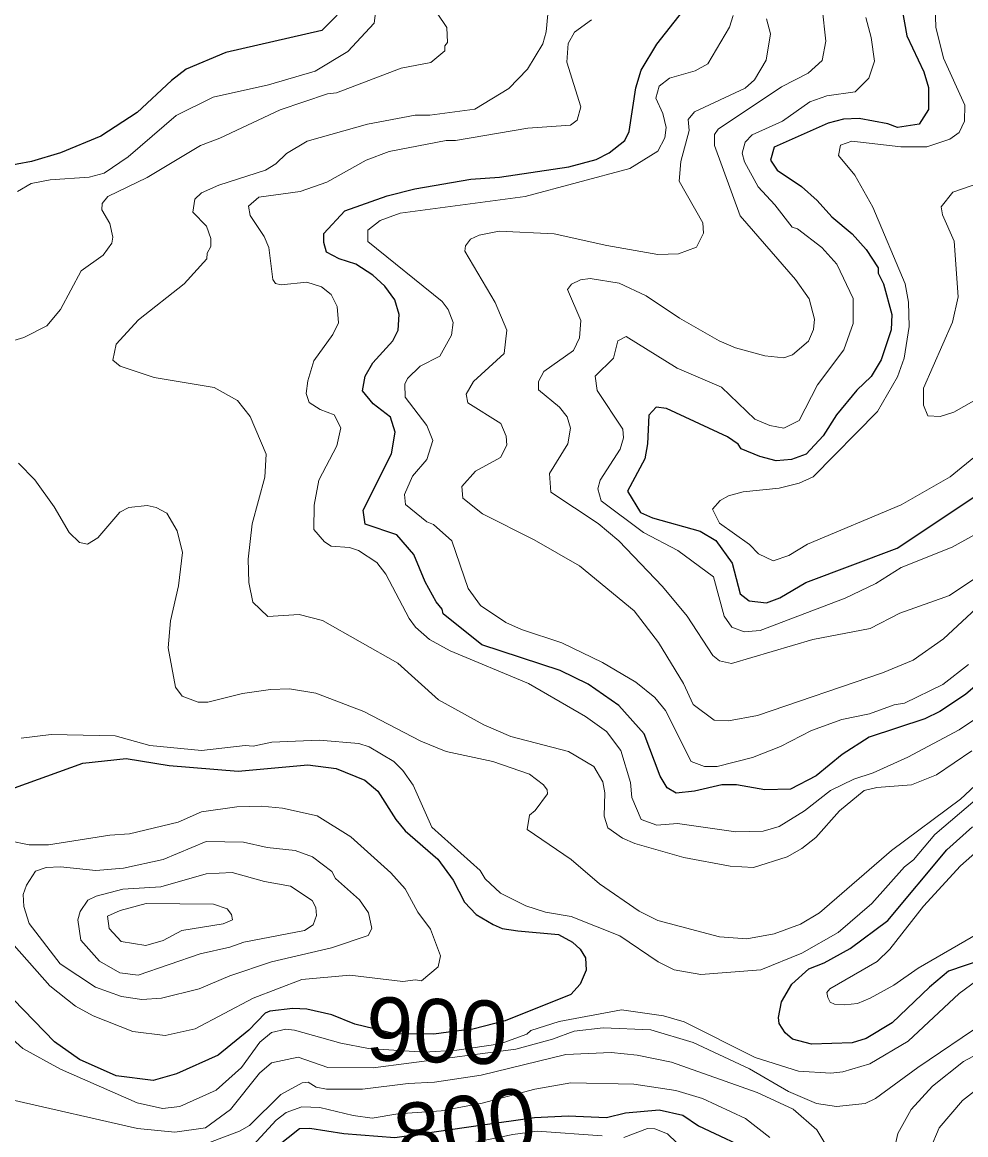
# Model space of a CAD drawing. Extents: x 673.3 to 698.5, y 6984.3 to 7012.3.
# Drawn here: x 685.086 to 686.277, y 6996.366 to 6997.77 of the extents above; entities that cross this region are included whole.
import ezdxf
from ezdxf.enums import TextEntityAlignment as Align

# ---------------------------------------------------------------- set-up
doc = ezdxf.new("R2010")
doc.units = 0
doc.header["$LTSCALE"] = 0.032
doc.layers.add('1', color=7, linetype='Continuous', lineweight=25)
doc.layers.add('2', color=7, linetype='Continuous', lineweight=13)
doc.layers.add('61', color=7, linetype='Continuous')

msp = doc.modelspace()

# ---------------------------------------------------------------- linework, layer by layer
at = {"layer": '1'}
for points in [[(686.3361, 6996.9726), (686.2772, 6996.9217), (686.2448, 6996.9002), (686.2259, 6996.8908), (686.1553, 6996.8677), (686.1213, 6996.8458), (686.0884, 6996.819), (686.0559, 6996.8018), (686.0239, 6996.801), (685.9881, 6996.8075), (685.9695, 6996.8075), (685.9349, 6996.7993), (685.9116, 6996.7969), (685.9005, 6996.8037), (685.8915, 6996.8185), (685.8713, 6996.8719), (685.8395, 6996.9077), (685.8004, 6996.9345), (685.7654, 6996.9517), (685.6662, 6996.9843), (685.6175, 6997.0232), (685.6162, 6997.0292), (685.6084, 6997.0386), (685.5946, 6997.0637), (685.5806, 6997.0983), (685.559, 6997.123), (685.519, 6997.1365), (685.5163, 6997.1544), (685.5521, 6997.2253), (685.5569, 6997.2529), (685.5511, 6997.2717), (685.529, 6997.2883), (685.5157, 6997.3049), (685.5189, 6997.3233), (685.5288, 6997.3403), (685.5537, 6997.3678), (685.5608, 6997.3813), (685.5618, 6997.4012), (685.5566, 6997.4198), (685.5439, 6997.437), (685.5287, 6997.4507), (685.5073, 6997.4647), (685.4861, 6997.4716), (685.4701, 6997.4801), (685.4666, 6997.4922), (685.4669, 6997.5035), (685.4933, 6997.5322), (685.5467, 6997.5511), (685.5815, 6997.5599), (685.6525, 6997.5723), (685.6884, 6997.5748), (685.776, 6997.5877), (685.8105, 6997.5968), (685.8271, 6997.6053), (685.8468, 6997.6211), (685.8525, 6997.6323), (685.8608, 6997.6874), (685.8676, 6997.7097), (685.8872, 6997.7426), (685.9311, 6997.7987)], [(686.1972, 6997.7859), (686.2029, 6997.753), (686.2247, 6997.7074), (686.2304, 6997.6879), (686.2305, 6997.6599), (686.2187, 6997.6414), (686.1914, 6997.6375), (686.1792, 6997.642), (686.1428, 6997.6488), (686.1229, 6997.648), (686.1035, 6997.643), (686.0356, 6997.6123), (686.031, 6997.5961), (686.0394, 6997.5834), (686.0699, 6997.5627), (686.0898, 6997.5451), (686.1082, 6997.5244), (686.1341, 6997.5032), (686.1518, 6997.4833), (686.1667, 6997.4601), (686.167, 6997.4533), (686.1735, 6997.44), (686.184, 6997.4012), (686.1832, 6997.3817), (686.1708, 6997.344), (686.1578, 6997.3228), (686.1398, 6997.3057), (686.1141, 6997.2747), (686.0975, 6997.2479), (686.0759, 6997.2248), (686.0575, 6997.218), (686.038, 6997.2164), (686.0174, 6997.2218), (685.9937, 6997.2318), (685.9899, 6997.2377), (685.9764, 6997.2469), (685.8994, 6997.2826), (685.8865, 6997.2844)], [(685.4837, 6997.7792), (685.4641, 6997.7596), (685.3431, 6997.7319), (685.293, 6997.711), (685.2743, 6997.6968), (685.2312, 6997.6562), (685.1851, 6997.6262), (685.134, 6997.6052), (685.0976, 6997.5944), (685.0613, 6997.5878)], [(685.8865, 6997.2844), (685.877, 6997.2742), (685.8754, 6997.238), (685.8721, 6997.2189), (685.8501, 6997.1784), (685.8665, 6997.1513), (685.8819, 6997.1447), (685.9422, 6997.1276), (685.9617, 6997.1161), (685.9826, 6997.0874), (685.9927, 6997.0487), (686.0041, 6997.0397), (686.026, 6997.0372), (686.0428, 6997.0436), (686.0755, 6997.0631), (686.1909, 6997.1063), (686.3064, 6997.1831)], [(685.0608, 6996.7981), (685.1623, 6996.8349), (685.2171, 6996.8409), (685.2714, 6996.8319), (685.3584, 6996.8247), (685.4467, 6996.8327), (685.4825, 6996.828), (685.5187, 6996.8132), (685.5349, 6996.7993), (685.5575, 6996.7638), (685.5695, 6996.7494), (685.6109, 6996.7136), (685.6301, 6996.6873), (685.6445, 6996.6592), (685.659, 6996.6437), (685.6805, 6996.6312), (685.692, 6996.6262), (685.7116, 6996.6232), (685.763, 6996.6186), (685.7809, 6996.6088), (685.7903, 6996.6001), (685.7972, 6996.5889), (685.7979, 6996.5736), (685.7905, 6996.5557), (685.7787, 6996.5426), (685.6956, 6996.5096), (685.6548, 6996.4991), (685.6334, 6996.4964), (685.6056, 6996.4928), (685.5565, 6996.4933), (685.506, 6996.5053), (685.4767, 6996.517), (685.4454, 6996.5241), (685.4278, 6996.5249), (685.3985, 6996.5218), (685.3925, 6996.5192), (685.3719, 6996.4978), (685.3334, 6996.4663), (685.2806, 6996.4426), (685.2512, 6996.434), (685.2046, 6996.4402), (685.1583, 6996.4606), (685.1267, 6996.4828), (685.0746, 6996.5366)], [(686.2992, 6996.587), (686.2558, 6996.5721), (686.2315, 6996.5522), (686.1846, 6996.5069), (686.1516, 6996.4873), (686.134, 6996.4817), (686.0825, 6996.4801), (686.0587, 6996.4864), (686.0495, 6996.4943), (686.0416, 6996.5063), (686.0408, 6996.5139), (686.0449, 6996.5333), (686.0577, 6996.5557), (686.0794, 6996.5751), (686.0985, 6996.5827), (686.1314, 6996.6008), (686.1789, 6996.6363), (686.2535, 6996.7256), (686.2858, 6996.7545)], [(685.3951, 6996.3411), (685.436, 6996.3734), (685.4489, 6996.3742), (685.4922, 6996.3671), (685.5564, 6996.3621), (685.6647, 6996.3776), (685.7329, 6996.3874), (685.7753, 6996.3895), (685.8236, 6996.3874), (685.8477, 6996.3933), (685.8902, 6996.3971), (685.9202, 6996.3905), (685.9398, 6996.377), (686.0151, 6996.3416)]]:
    msp.add_lwpolyline(points, dxfattribs=at)
at = {"layer": '2'}
for points in [[(685.0798, 6997.5567), (685.0971, 6997.5666), (685.1211, 6997.5714), (685.1704, 6997.5747), (685.1894, 6997.5795), (685.2197, 6997.6001), (685.2801, 6997.6525), (685.3271, 6997.6757), (685.3968, 6997.6912), (685.4558, 6997.7085), (685.4972, 6997.7334), (685.5301, 6997.7689), (685.5349, 6997.8062)], [(686.1912, 6997.3227), (686.1996, 6997.3462), (686.206, 6997.3862), (686.2053, 6997.4168), (686.2011, 6997.44), (686.1603, 6997.5367), (686.1374, 6997.5773), (686.1167, 6997.6018), (686.1191, 6997.6152), (686.1337, 6997.6202), (686.1956, 6997.613), (686.2285, 6997.613), (686.2575, 6997.6225), (686.2693, 6997.6309), (686.2758, 6997.6452), (686.2761, 6997.6656), (686.2494, 6997.7247), (686.2395, 6997.7641), (686.2385, 6997.8042)], [(685.0567, 6997.363), (685.0877, 6997.3721), (685.1169, 6997.3871), (685.1342, 6997.4077), (685.1603, 6997.4564), (685.188, 6997.4762), (685.1991, 6997.4912), (685.2002, 6997.4989), (685.1964, 6997.5163), (685.1865, 6997.5334), (685.1866, 6997.5412), (685.1938, 6997.5501), (685.2437, 6997.574), (685.3108, 6997.6148), (685.3352, 6997.6238), (685.4117, 6997.6597), (685.4714, 6997.6797), (685.4826, 6997.6813), (685.5643, 6997.7123), (685.602, 6997.7195), (685.6194, 6997.7343), (685.6197, 6997.7405), (685.6229, 6997.7448), (685.622, 6997.7636), (685.6097, 6997.7817)], [(685.8398, 6997.441), (685.8737, 6997.4248), (685.9158, 6997.3967), (685.9662, 6997.3679), (685.9868, 6997.3592), (686.0236, 6997.349), (686.0475, 6997.3465), (686.0587, 6997.3505), (686.0789, 6997.3676), (686.0852, 6997.3825), (686.0864, 6997.3952), (686.0795, 6997.421), (686.0624, 6997.4455), (685.9924, 6997.5256), (685.9601, 6997.6147), (685.9601, 6997.6284), (685.9646, 6997.6352), (686.0447, 6997.6885), (686.0784, 6997.706), (686.0962, 6997.7219), (686.1009, 6997.7462), (686.096, 6997.7885)], [(685.7498, 6997.7802), (685.7476, 6997.7582), (685.7433, 6997.7429), (685.7241, 6997.711), (685.7004, 6997.6864), (685.6574, 6997.6603), (685.6005, 6997.653), (685.5819, 6997.6528), (685.5219, 6997.6414), (685.4456, 6997.6199), (685.4196, 6997.6044), (685.4061, 6997.5916), (685.393, 6997.5835), (685.3343, 6997.5647), (685.3121, 6997.5547), (685.3037, 6997.5468), (685.3013, 6997.5306), (685.3185, 6997.5128), (685.324, 6997.497), (685.324, 6997.487), (685.3192, 6997.4786), (685.3188, 6997.4716), (685.2905, 6997.44), (685.2326, 6997.3945), (685.2044, 6997.3637), (685.2003, 6997.3437), (685.2095, 6997.3359), (685.2526, 6997.3219), (685.3284, 6997.309), (685.3576, 6997.2927), (685.3737, 6997.2725), (685.394, 6997.225), (685.3924, 6997.196), (685.3764, 6997.137), (685.3713, 6997.0924), (685.3721, 6997.0627), (685.3769, 6997.0379), (685.396, 6997.0201), (685.4356, 6997.0225), (685.4649, 6997.0151), (685.5604, 6996.961), (685.6117, 6996.9147)], [(685.9836, 6997.7789), (685.9791, 6997.7642), (685.9515, 6997.7179), (685.9359, 6997.7088), (685.9033, 6997.6994), (685.8902, 6997.6897), (685.886, 6997.6743), (685.895, 6997.655), (685.8989, 6997.6372), (685.8975, 6997.6242), (685.8886, 6997.6074), (685.8532, 6997.5855), (685.7209, 6997.5503), (685.563, 6997.5291), (685.538, 6997.52), (685.5221, 6997.5079), (685.5222, 6997.4932), (685.6162, 6997.4177), (685.6238, 6997.4075), (685.6302, 6997.3911), (685.6278, 6997.3751), (685.6132, 6997.3487), (685.5886, 6997.3359), (685.5725, 6997.3205), (685.569, 6997.3132), (685.5695, 6997.297), (685.5968, 6997.2611), (685.6042, 6997.2423), (685.5968, 6997.2182), (685.5787, 6997.1971), (685.5687, 6997.1741), (685.57, 6997.1612), (685.5968, 6997.1395), (685.6051, 6997.1363), (685.6284, 6997.1154), (685.6492, 6997.0554), (685.6644, 6997.034), (685.6967, 6997.0124), (685.7164, 6997.0035), (685.7674, 6996.9869), (685.8187, 6996.9621), (685.8607, 6996.937), (685.8849, 6996.9176), (685.8981, 6996.9012), (685.9306, 6996.8371), (685.9475, 6996.8308)], [(686.3491, 6997.0842), (686.2495, 6996.9919), (686.2112, 6996.9649), (686.1725, 6996.9487), (686.0143, 6996.8951), (685.9776, 6996.8883), (685.9595, 6996.889), (685.9332, 6996.9088), (685.9209, 6996.9354), (685.8894, 6996.9873), (685.8586, 6997.0271), (685.7896, 6997.0838), (685.7323, 6997.1168), (685.6672, 6997.1494), (685.6422, 6997.1695), (685.6409, 6997.1843), (685.6582, 6997.2034), (685.6899, 6997.2209), (685.6978, 6997.2362), (685.697, 6997.2478), (685.6904, 6997.2636), (685.6488, 6997.2898), (685.6467, 6997.3007), (685.6557, 6997.3167), (685.6946, 6997.3519), (685.6979, 6997.3816), (685.683, 6997.4162), (685.645, 6997.481), (685.6457, 6997.4878), (685.6521, 6997.4962), (685.6631, 6997.5013), (685.6882, 6997.5063), (685.7578, 6997.5031), (685.824, 6997.4882), (685.8887, 6997.4769), (685.9148, 6997.4778), (685.9373, 6997.4862), (685.9462, 6997.5041), (685.9454, 6997.5168), (685.9153, 6997.5694), (685.9176, 6997.5944), (685.9282, 6997.6334), (685.9269, 6997.6474), (685.9347, 6997.6572), (685.9989, 6997.6869), (686.0106, 6997.6977), (686.0253, 6997.7224), (686.0308, 6997.7556), (686.026, 6997.7745)], [(685.7736, 6997.7198), (685.7754, 6997.7432), (685.7833, 6997.7577), (685.8046, 6997.7733)], [(686.1511, 6997.776), (686.158, 6997.7511), (686.162, 6997.7211), (686.1549, 6997.6996), (686.1376, 6997.6822), (686.1018, 6997.6772), (686.0806, 6997.6699), (686.0462, 6997.6454), (686.0079, 6997.628), (685.9988, 6997.6187), (685.9951, 6997.6048), (685.9981, 6997.5939), (686.0151, 6997.5625), (686.0364, 6997.5399), (686.0584, 6997.5114), (686.0651, 6997.5095), (686.0956, 6997.4857), (686.1148, 6997.4647), (686.1353, 6997.4214), (686.1351, 6997.3898), (686.1234, 6997.3567), (686.09, 6997.3126), (686.067, 6997.2673), (686.0478, 6997.2579), (686.0298, 6997.2612), (686.0112, 6997.2689), (685.9688, 6997.3095), (685.913, 6997.3336), (685.8484, 6997.3733), (685.8381, 6997.368), (685.8327, 6997.3463), (685.8095, 6997.3235), (685.8119, 6997.3054), (685.8443, 6997.2565), (685.8452, 6997.2455), (685.841, 6997.2311), (685.8157, 6997.192), (685.8127, 6997.181), (685.8168, 6997.1659), (685.8703, 6997.1261), (685.9138, 6997.1033)], [(686.2909, 6996.8916), (686.269, 6996.8769), (686.2044, 6996.8425), (686.1605, 6996.8228), (686.136, 6996.8148), (686.1067, 6996.8002), (686.0736, 6996.7746), (686.0418, 6996.7547), (686.0217, 6996.7488), (685.9872, 6996.7481), (685.9135, 6996.7585), (685.8873, 6996.7564), (685.8674, 6996.7639), (685.8558, 6996.7915), (685.8541, 6996.8106), (685.842, 6996.8507), (685.8238, 6996.8747), (685.7972, 6996.8938), (685.7253, 6996.9355), (685.6265, 6996.9768), (685.6003, 6996.9909), (685.5827, 6997.0065), (685.5747, 6997.0174), (685.5449, 6997.0736), (685.5337, 6997.0882), (685.5105, 6997.1031), (685.4991, 6997.1072), (685.4758, 6997.1089), (685.4676, 6997.1144), (685.4543, 6997.1298), (685.4544, 6997.1607), (685.4604, 6997.192), (685.4832, 6997.2356), (685.4884, 6997.2581), (685.4799, 6997.2746), (685.4623, 6997.2812), (685.4483, 6997.2902), (685.4446, 6997.3013), (685.4467, 6997.3176), (685.4543, 6997.3429), (685.478, 6997.3758), (685.4852, 6997.3907), (685.4835, 6997.4115), (685.4761, 6997.4266), (685.4636, 6997.4363), (685.4451, 6997.4419), (685.413, 6997.4387), (685.4057, 6997.4402), (685.4022, 6997.4455), (685.3973, 6997.4859), (685.3915, 6997.4997), (685.3739, 6997.5264), (685.3714, 6997.538), (685.3845, 6997.5494), (685.4369, 6997.5567), (685.4704, 6997.5684), (685.5201, 6997.5961), (685.5494, 6997.6072), (685.6211, 6997.6211), (685.6329, 6997.6211), (685.7242, 6997.6366), (685.7781, 6997.6401), (685.7867, 6997.6467), (685.7914, 6997.6634), (685.7736, 6997.7198)], [(686.3157, 6997.3082), (686.2624, 6997.278), (686.2451, 6997.2726), (686.2297, 6997.2735), (686.224, 6997.2869), (686.224, 6997.3084), (686.2606, 6997.3917), (686.2679, 6997.4234), (686.263, 6997.494), (686.2482, 6997.5269), (686.2466, 6997.537), (686.2611, 6997.5558), (686.3158, 6997.5745)], [(686.2938, 6997.0713), (686.2568, 6997.0463), (686.1944, 6997.024), (686.1566, 6997.005), (686.0842, 6996.9908), (685.9818, 6996.9607), (685.9666, 6996.9641), (685.9579, 6996.9708), (685.9256, 6997.0204), (685.8945, 6997.058), (685.8394, 6997.1153), (685.8133, 6997.1375), (685.7533, 6997.1768), (685.7516, 6997.2005), (685.7751, 6997.238), (685.7784, 6997.2579), (685.7741, 6997.2722), (685.7643, 6997.2842), (685.7379, 6997.3061), (685.7378, 6997.3165), (685.7447, 6997.3291), (685.7819, 6997.3559), (685.7897, 6997.3717), (685.7915, 6997.3936), (685.7746, 6997.4328), (685.7794, 6997.4394), (685.7911, 6997.4451), (685.8029, 6997.4469), (685.8398, 6997.441)], [(686.2921, 6997.2243), (686.2579, 6997.1961), (686.1959, 6997.1608), (686.0776, 6997.1114), (686.0539, 6997.0971), (686.0341, 6997.0903), (686.0156, 6997.0992), (686.0042, 6997.111), (685.9665, 6997.1376), (685.9578, 6997.1555), (685.9673, 6997.1665), (685.9778, 6997.1725), (685.9963, 6997.1773), (686.0419, 6997.1822), (686.0671, 6997.1884), (686.0846, 6997.1963), (686.1658, 6997.2788), (686.1912, 6997.3227)], [(685.7442, 6996.8075), (685.7265, 6996.8208), (685.6802, 6996.8368), (685.6212, 6996.8497), (685.5893, 6996.8627), (685.5173, 6996.9002), (685.4568, 6996.9231), (685.4232, 6996.9288), (685.3992, 6996.928), (685.3639, 6996.9228), (685.3203, 6996.9118), (685.3082, 6996.9119), (685.288, 6996.9196), (685.2793, 6996.9308), (685.2703, 6996.9805), (685.2729, 6997.0147), (685.2832, 6997.0586), (685.2882, 6997.1007), (685.2814, 6997.1282), (685.2686, 6997.1504), (685.2551, 6997.1576), (685.2437, 6997.1601), (685.2204, 6997.1576), (685.209, 6997.1518), (685.1815, 6997.1195), (685.1684, 6997.1113), (685.1582, 6997.1133), (685.145, 6997.1262), (685.1263, 6997.1583), (685.1019, 6997.1925), (685.081, 6997.2135)], [(685.9138, 6997.1033), (685.9588, 6997.0701), (685.9725, 6997.0205), (685.9819, 6997.0066), (685.9976, 6997.0006), (686.0176, 6997.0022), (686.1253, 6997.0431), (686.1637, 6997.0617), (686.196, 6997.0818), (686.2604, 6997.1075), (686.3073, 6997.1334)], [(685.9475, 6996.8308), (685.9633, 6996.8304), (686.0083, 6996.8421), (686.0434, 6996.8557), (686.0825, 6996.876), (686.1208, 6996.8898), (686.1558, 6996.8972), (686.1872, 6996.9083), (686.2002, 6996.9104), (686.2487, 6996.934), (686.2811, 6996.9592)], [(685.6117, 6996.9147), (685.6687, 6996.8833), (685.703, 6996.8686), (685.7757, 6996.8497), (685.8076, 6996.8305), (685.8192, 6996.8113), (685.8216, 6996.7972), (685.8209, 6996.7677), (685.8256, 6996.7532), (685.8438, 6996.7403), (685.8594, 6996.7333), (685.9214, 6996.7158), (685.9799, 6996.7049), (686.0092, 6996.7033), (686.0517, 6996.7166), (686.0705, 6996.7271), (686.0882, 6996.741), (686.1179, 6996.7747), (686.1491, 6996.8001), (686.1653, 6996.8042), (686.209, 6996.8075), (686.2405, 6996.8199), (686.2852, 6996.8502)], [(685.6706, 6996.6889), (685.6642, 6996.6994), (685.6032, 6996.754), (685.5796, 6996.807), (685.5665, 6996.8257), (685.5551, 6996.837), (685.5242, 6996.8555), (685.511, 6996.8596), (685.4607, 6996.8638), (685.4012, 6996.8612), (685.3773, 6996.8564), (685.3672, 6996.8572), (685.3122, 6996.8506), (685.247, 6996.8572), (685.203, 6996.8694), (685.1224, 6996.8711), (685.0844, 6996.8662)], [(686.364, 6996.8759), (686.2708, 6996.7893), (686.1838, 6996.7244), (686.0926, 6996.6458), (686.0689, 6996.6315), (686.0353, 6996.6195), (686.0011, 6996.613), (685.9664, 6996.6154), (685.8885, 6996.636), (685.8651, 6996.6481), (685.8149, 6996.6823), (685.7791, 6996.7132), (685.7235, 6996.751), (685.7264, 6996.7692), (685.7338, 6996.7752), (685.7492, 6996.7962), (685.749, 6996.801), (685.7442, 6996.8075)], [(686.2894, 6996.7881), (686.2383, 6996.7446), (686.2114, 6996.7127), (686.2002, 6996.7039), (686.1587, 6996.6576), (686.1162, 6996.6209), (686.0706, 6996.5948), (686.0185, 6996.5741), (685.9429, 6996.5681), (685.9091, 6996.574), (685.889, 6996.584), (685.8406, 6996.6168), (685.7791, 6996.6414), (685.7465, 6996.6467), (685.7217, 6996.6545), (685.6898, 6996.6709), (685.6706, 6996.6889)], [(685.0697, 6996.7366), (685.0944, 6996.7318), (685.119, 6996.7318), (685.1965, 6996.7441), (685.2212, 6996.7457), (685.2826, 6996.7603), (685.3121, 6996.7734), (685.3568, 6996.7798), (685.388, 6996.7807), (685.4147, 6996.7782), (685.4582, 6996.7685), (685.5007, 6996.7417), (685.5514, 6996.6965), (685.5693, 6996.6762), (685.5856, 6996.6469), (685.6013, 6996.6253), (685.6139, 6996.5915), (685.6112, 6996.5775), (685.5901, 6996.56), (685.5825, 6996.5614), (685.5666, 6996.5592), (685.4997, 6996.5673), (685.4389, 6996.5615), (685.3776, 6996.5382), (685.3041, 6996.4996), (685.2665, 6996.4908), (685.2257, 6996.4961), (685.1756, 6996.5157), (685.1531, 6996.5282), (685.1209, 6996.5538), (685.0758, 6996.6046)], [(686.3033, 6996.7339), (686.2708, 6996.7054), (686.224, 6996.6544), (686.1817, 6996.6001), (686.1655, 6996.5846), (686.1056, 6996.5499), (686.1019, 6996.5451), (686.1031, 6996.539), (686.1062, 6996.5329), (686.1118, 6996.5306), (686.1249, 6996.5299), (686.1408, 6996.5316), (686.1566, 6996.5382), (686.1867, 6996.5544), (686.2174, 6996.5759), (686.2921, 6996.6193)], [(685.051, 6996.5064), (685.0868, 6996.4746), (685.1343, 6996.4483), (685.231, 6996.4058), (685.2629, 6996.3989), (685.2847, 6996.4013), (685.3309, 6996.422), (685.3628, 6996.4505), (685.3859, 6996.4824), (685.4007, 6996.4948), (685.4187, 6996.4988), (685.4297, 6996.4979), (685.4883, 6996.4812), (685.523, 6996.4745), (685.594, 6996.4699), (685.6347, 6996.4725), (685.6895, 6996.4803), (685.7231, 6996.4927), (685.7283, 6996.4972), (685.7641, 6996.5087), (685.8428, 6996.5233), (685.8956, 6996.5158), (685.9217, 6996.5084), (686.0116, 6996.4633), (686.0662, 6996.4459), (686.1069, 6996.4435), (686.1223, 6996.4453), (686.1561, 6996.4554), (686.2049, 6996.4839), (686.2693, 6996.5441), (686.3137, 6996.5767)], [(685.0726, 6996.4098), (685.2314, 6996.3735), (685.2787, 6996.369), (685.3174, 6996.3743), (685.3489, 6996.3975), (685.3857, 6996.4433), (685.4006, 6996.4567), (685.4342, 6996.4637), (685.4717, 6996.4508), (685.5291, 6996.4501), (685.7094, 6996.4738), (685.7557, 6996.4864), (685.7828, 6996.4965), (685.8194, 6996.5005), (685.8797, 6996.4981), (685.933, 6996.4823), (686.0043, 6996.449), (686.0535, 6996.4204), (686.089, 6996.4052), (686.1142, 6996.4012), (686.1503, 6996.4052), (686.1634, 6996.4113), (686.2168, 6996.4507), (686.3014, 6996.5078)], [(686.3415, 6996.4941), (686.2747, 6996.4583), (686.2353, 6996.4272), (686.2083, 6996.3977), (686.1915, 6996.3672), (686.1816, 6996.3216)], [(686.1276, 6996.3078), (686.0892, 6996.372), (686.0594, 6996.3978), (686.0141, 6996.4189), (685.906, 6996.4574), (685.8626, 6996.4663), (685.8298, 6996.4696), (685.7725, 6996.4671), (685.6656, 6996.4411), (685.6063, 6996.432), (685.5734, 6996.4304), (685.5154, 6996.4231), (685.4701, 6996.4231), (685.4569, 6996.4256), (685.447, 6996.432), (685.4395, 6996.4313), (685.4126, 6996.4164), (685.3727, 6996.3774), (685.3604, 6996.3701), (685.3225, 6996.3558)], [(686.2734, 6996.4091), (686.3243, 6996.4486)], [(685.3677, 6996.3422), (685.4066, 6996.3842), (685.4193, 6996.3938), (685.439, 6996.4011), (685.4617, 6996.4003), (685.5038, 6996.3898), (685.5279, 6996.3865), (685.5604, 6996.3921), (685.6151, 6996.3961), (685.6666, 6996.4054), (685.7334, 6996.4233), (685.7787, 6996.4312), (685.8581, 6996.4296), (685.9115, 6996.4215), (685.9449, 6996.4113), (685.9992, 6996.3864), (686.0299, 6996.3622)], [(686.2325, 6996.3474), (686.2439, 6996.3746), (686.2734, 6996.4091)], [(685.8184, 6996.3645), (685.7363, 6996.3702), (685.7053, 6996.366), (685.6296, 6996.3503)], [(685.9245, 6996.344), (685.9006, 6996.3669), (685.8846, 6996.3732), (685.8754, 6996.3734), (685.8456, 6996.3624)]]:
    msp.add_lwpolyline(points, dxfattribs=at)
for points in [[(685.0944, 6996.6326), (685.0878, 6996.6539), (685.0871, 6996.669), (685.0914, 6996.6809), (685.1028, 6996.6985), (685.1162, 6996.7031), (685.1343, 6996.7041), (685.1789, 6996.6993), (685.2139, 6996.7024), (685.264, 6996.7134), (685.3183, 6996.736), (685.3654, 6996.7351), (685.3952, 6996.7285), (685.4304, 6996.7245), (685.4525, 6996.7164), (685.4767, 6996.6979), (685.4816, 6996.689), (685.5117, 6996.6621), (685.5233, 6996.6459), (685.5275, 6996.626), (685.5228, 6996.6172), (685.4766, 6996.6016), (685.4005, 6996.5841), (685.348, 6996.5665), (685.3093, 6996.5499), (685.2619, 6996.5383), (685.2367, 6996.5364), (685.2111, 6996.5404), (685.1782, 6996.552), (685.1336, 6996.5813)], [(685.1562, 6996.6369), (685.159, 6996.6477), (685.1686, 6996.6617), (685.1792, 6996.667), (685.2128, 6996.6756), (685.2609, 6996.6785), (685.3183, 6996.6951), (685.3509, 6996.6967), (685.3916, 6996.6854), (685.4245, 6996.6795), (685.4522, 6996.6613), (685.4565, 6996.6525), (685.4576, 6996.6425), (685.4533, 6996.6307), (685.4422, 6996.6235), (685.3659, 6996.6089), (685.348, 6996.6024), (685.3105, 6996.5942), (685.2323, 6996.5673), (685.209, 6996.5701), (685.1835, 6996.5847), (685.1597, 6996.6113)], [(685.1936, 6996.6416), (685.2095, 6996.6488), (685.2424, 6996.6575), (685.3275, 6996.6569), (685.3446, 6996.6509), (685.3501, 6996.6438), (685.3516, 6996.6371), (685.3396, 6996.6321), (685.2875, 6996.6234), (685.264, 6996.611), (685.2421, 6996.6048), (685.2109, 6996.6097), (685.1955, 6996.6261)]]:
    msp.add_lwpolyline(points, close=True, dxfattribs=at)

# ---------------------------------------------------------------- texts
at = {"layer": '61'}
for s, rotation, p in [('900', 358.159, (685.6081, 6996.4571)), ('800', 8.017, (685.6505, 6996.3353))]:
    msp.add_text(s, height=0.08, rotation=rotation, dxfattribs=at).set_placement(p, align=Align.CENTER)

doc.saveas('drawing.dxf')
